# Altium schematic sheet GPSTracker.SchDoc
size B
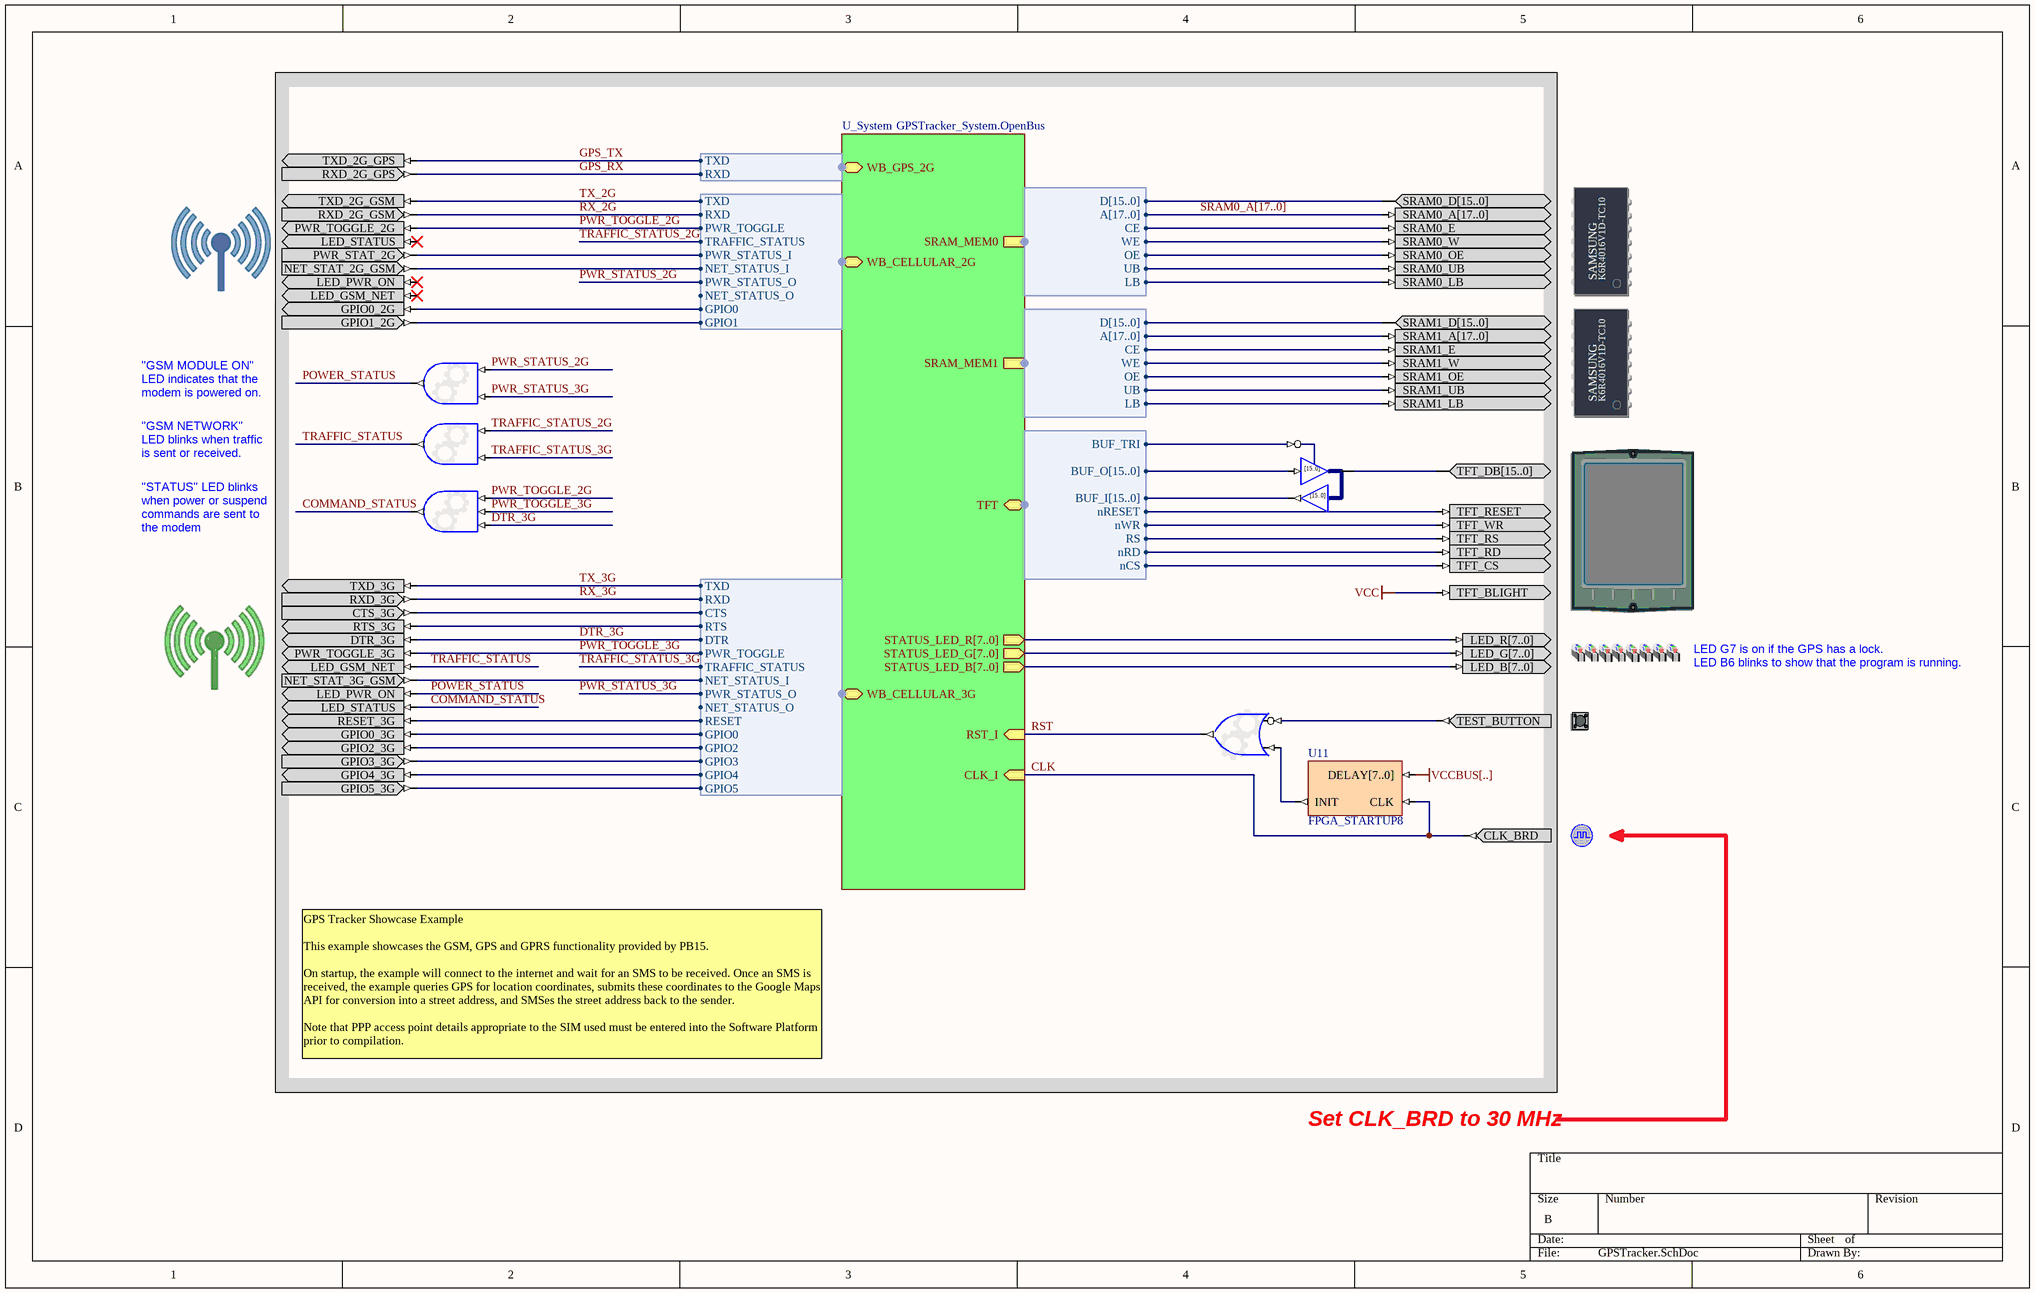
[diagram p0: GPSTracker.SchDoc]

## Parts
(Parts that share a designator on the sheet are numbered #1, #2 ... from top to bottom, then left to right.)
*  3G_GSM_GPS_COMP  (value not drawn)
?#1  2G_GPS_COMP  (value not drawn)
?#2  SRAM_DAUGHTER0  (value not drawn)
?#3  2G_GSM_COMP  (value not drawn)
?#4  SRAM_DAUGHTER1  (value not drawn)
?#5  TFT_LCD  (value not drawn)
?#6  LEDS_RGB  (value not drawn)
?#7  TEST_BUTTON  (value not drawn)
?#8  CLOCK_BOARD  (value not drawn)
U4  IOBUF16B  (value not drawn)
U6  OR2S  (value not drawn)
U7  AND3S  (value not drawn)
U8  AND2S  (value not drawn)
U9  AND2S  (value not drawn)
U11  FPGA_STARTUP8

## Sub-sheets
U_System = GPSTracker_System.OpenBus: SRAM_MEM0 (harness WB_MEM_CTRL_SRAM16_A18), SRAM_MEM1 (harness WB_MEM_CTRL_SRAM16_A18), RST_I (in), CLK_I (in), TFT (harness VGA32_ILI9320), WB_CELLULAR_2G (harness WB_CELLULAR_2G), WB_CELLULAR_3G (harness WB_CELLULAR_3G), WB_GPS_2G (harness WB_GPS_NMEA), STATUS_LED_R[7..0] (out), STATUS_LED_G[7..0] (out), STATUS_LED_B[7..0] (out)

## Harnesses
WB_MEM_CTRL_SRAM16_A18: D[15..0], A[17..0], CE, WE, OE, UB, LB
VGA32_ILI9320: BUF_TRI, BUF_O[15..0], BUF_I[15..0], nRESET, nWR, RS, nRD, nCS
WB_CELLULAR_2G: TXD, RXD, PWR_TOGGLE, TRAFFIC_STATUS, PWR_STATUS_I, NET_STATUS_I, PWR_STATUS_O, NET_STATUS_O, GPIO0, GPIO1
WB_CELLULAR_3G: TXD, RXD, CTS, RTS, DTR, PWR_TOGGLE, TRAFFIC_STATUS, NET_STATUS_I, PWR_STATUS_O, NET_STATUS_O, RESET, GPIO0, GPIO2, GPIO3, GPIO4, GPIO5
WB_GPS_NMEA: RXD, TXD

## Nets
VCC: ?#5.TFT_BLIGHT
VCCBUS[..]: U11.DELAY[7..0]
CLK: ?#8.CLK_BRD U11.CLK ; sheet U_System/CLK_I
COMMAND_STATUS: *.LED_STATUS U7.O
DTR_3G: *.DTR_3G U7.I2 ; sheet U_System/WB_CELLULAR_3G.DTR
GPS_RX: ?#1.RXD_2G_GPS ; sheet U_System/WB_GPS_2G.RXD
GPS_TX: ?#1.TXD_2G_GPS ; sheet U_System/WB_GPS_2G.TXD
POWER_STATUS: *.LED_PWR_ON U9.O
PWR_STATUS_2G: U9.I0 ; sheet U_System/WB_CELLULAR_2G.PWR_STATUS_O
PWR_STATUS_3G: U9.I1 ; sheet U_System/WB_CELLULAR_3G.PWR_STATUS_O
PWR_TOGGLE_2G: ?#3.PWR_TOGGLE_2G U7.I0 ; sheet U_System/WB_CELLULAR_2G.PWR_TOGGLE
PWR_TOGGLE_3G: *.PWR_TOGGLE_3G U7.I1 ; sheet U_System/WB_CELLULAR_3G.PWR_TOGGLE
RST: U6.O ; sheet U_System/RST_I
RX_2G: ?#3.RXD_2G_GSM ; sheet U_System/WB_CELLULAR_2G.RXD
RX_3G: *.RXD_3G ; sheet U_System/WB_CELLULAR_3G.RXD
TRAFFIC_STATUS: *.LED_GSM_NET U8.O
TRAFFIC_STATUS_2G: U8.I0 ; sheet U_System/WB_CELLULAR_2G.TRAFFIC_STATUS
TRAFFIC_STATUS_3G: U8.I1 ; sheet U_System/WB_CELLULAR_3G.TRAFFIC_STATUS
TX_2G: ?#3.TXD_2G_GSM ; sheet U_System/WB_CELLULAR_2G.TXD
TX_3G: *.TXD_3G ; sheet U_System/WB_CELLULAR_3G.TXD
Net*_CTS_3G: *.CTS_3G ; sheet U_System/WB_CELLULAR_3G.CTS
Net*_GPIO0_3G: *.GPIO0_3G ; sheet U_System/WB_CELLULAR_3G.GPIO0
Net*_GPIO2_3G: *.GPIO2_3G ; sheet U_System/WB_CELLULAR_3G.GPIO2
Net*_GPIO3_3G: *.GPIO3_3G ; sheet U_System/WB_CELLULAR_3G.GPIO3
Net*_GPIO4_3G: *.GPIO4_3G ; sheet U_System/WB_CELLULAR_3G.GPIO4
Net*_GPIO5_3G: *.GPIO5_3G ; sheet U_System/WB_CELLULAR_3G.GPIO5
Net*_NET_STAT_3G_GSM: *.NET_STAT_3G_GSM ; sheet U_System/WB_CELLULAR_3G.NET_STATUS_I
Net*_RESET_3G: *.RESET_3G ; sheet U_System/WB_CELLULAR_3G.RESET
Net*_RTS_3G: *.RTS_3G ; sheet U_System/WB_CELLULAR_3G.RTS
Net?#2_SRAM0_E: ?#2.SRAM0_E ; sheet U_System/SRAM_MEM0.CE
Net?#2_SRAM0_LB: ?#2.SRAM0_LB ; sheet U_System/SRAM_MEM0.LB
Net?#2_SRAM0_OE: ?#2.SRAM0_OE ; sheet U_System/SRAM_MEM0.OE
Net?#2_SRAM0_UB: ?#2.SRAM0_UB ; sheet U_System/SRAM_MEM0.UB
Net?#2_SRAM0_W: ?#2.SRAM0_W ; sheet U_System/SRAM_MEM0.WE
Net?#3_GPIO0_2G: ?#3.GPIO0_2G ; sheet U_System/WB_CELLULAR_2G.GPIO0
Net?#3_GPIO1_2G: ?#3.GPIO1_2G ; sheet U_System/WB_CELLULAR_2G.GPIO1
Net?#3_NET_STAT_2G_GSM: ?#3.NET_STAT_2G_GSM ; sheet U_System/WB_CELLULAR_2G.NET_STATUS_I
Net?#3_PWR_STAT_2G: ?#3.PWR_STAT_2G ; sheet U_System/WB_CELLULAR_2G.PWR_STATUS_I
Net?#4_SRAM1_E: ?#4.SRAM1_E ; sheet U_System/SRAM_MEM1.CE
Net?#4_SRAM1_LB: ?#4.SRAM1_LB ; sheet U_System/SRAM_MEM1.LB
Net?#4_SRAM1_OE: ?#4.SRAM1_OE ; sheet U_System/SRAM_MEM1.OE
Net?#4_SRAM1_UB: ?#4.SRAM1_UB ; sheet U_System/SRAM_MEM1.UB
Net?#4_SRAM1_W: ?#4.SRAM1_W ; sheet U_System/SRAM_MEM1.WE
Net?#5_TFT_CS: ?#5.TFT_CS ; sheet U_System/TFT.nCS
Net?#5_TFT_RD: ?#5.TFT_RD ; sheet U_System/TFT.nRD
Net?#5_TFT_RESET: ?#5.TFT_RESET ; sheet U_System/TFT.nRESET
Net?#5_TFT_RS: ?#5.TFT_RS ; sheet U_System/TFT.RS
Net?#5_TFT_WR: ?#5.TFT_WR ; sheet U_System/TFT.nWR
Net?#7_TEST_BUTTON: ?#7.TEST_BUTTON U6.I0
NetU4_T: U4.T ; sheet U_System/TFT.BUF_TRI
NetU6_I1: U6.I1 U11.INIT

Not connected (* = marked no-connect by the designer): ?#2 SRAM0_A[17..0] SRAM0_D[15..0]; ?#3 LED_GSM_NET* LED_PWR_ON* LED_STATUS*; ?#4 SRAM1_A[17..0] SRAM1_D[15..0]; ?#5 TFT_DB[15..0]; ?#6 LED_B[7..0] LED_G[7..0] LED_R[7..0]; U4 I[15..0] IO[15..0] O[15..0]

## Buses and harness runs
bus SRAM0_A[17..0]

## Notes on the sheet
- "GSM MODULE ON"
  LED indicates that the modem is powered on.
- "GSM NETWORK"
  LED blinks when traffic is sent or received.
- "STATUS" LED blinks when power or suspend commands are sent to the modem
- LED G7 is on if the GPS has a lock.
  LED B6 blinks to show that the program is running.
- GPS Tracker Showcase Example
  This example showcases the GSM, GPS and GPRS functionality provided by PB15.
  On startup, the example will connect to the internet and wait for an SMS to be received. Once an SMS is received, the example queries GPS for location coordinates, submits these coordinates to the Google Maps API for conversion into a street address, and SMSes the street address back to the sender.
  Note that PPP access point details appropriate to the SIM used must be entered into the Software Platform prior to compilation.
- Set CLK_BRD to 30 MHz

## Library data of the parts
* = 3G_GSM_GPS_COMP: 3G GSM/GPRS/GPS Component; PortComponent: TRUE
?#1 = 2G_GPS_COMP: 2G GPS Component; PortComponent: True
?#2 = SRAM_DAUGHTER0: Free Static RAM - Daughterboard; PortComponent: True
?#3 = 2G_GSM_COMP: 2G GSM/GPRS Component; PortComponent: True
?#4 = SRAM_DAUGHTER1: Free Static RAM - Daughterboard; PortComponent: True
?#5 = TFT_LCD: TFT LCD Panel; PortComponent: True
?#6 = LEDS_RGB: LEDS RGB; PortComponent: True
?#7 = TEST_BUTTON: Test / Reset Button; PortComponent: True
?#8 = CLOCK_BOARD: Global System Clock Supply; PortComponent: True
U4 = IOBUF16B: 16-Bit Input/Output Buffer, Bus Version; SubClass: IOBUF; Enable: Low; Control: Common Control T; PortSize: 16; ArchiveName: GENERIC; VHDLIB_SIM: GENERIC_LIB
U6 = GATE: Configurable Generic Gate; ConfiguratorName: GENERIC_GATE; ConfigurationParameters: {}Version[1.0]{}GateKind[OR]{}BusInput[False]{}GateInputType[Bit]{}GateOutputOption[Normal]{}BusWidth[8]{}RegisterOutputs[False]{}NegativeClockEdge[False]{}InputCount[2]{}InputInvert0[True]{}InputInvert1[False]{}
U7 = GATE: Configurable Generic Gate; ConfiguratorName: GENERIC_GATE; ConfigurationParameters: {}Version[1.1]{}GateKind[AND]{}BusInput[False]{}GateInputType[Bit]{}GateOutputOption[Normal]{}BusWidth[8]{}RegisterOutputs[False]{}NegativeClockEdge[False]{}InputCount[3]{}InputInvert0[False]{}InputInvert1[False]{}InputInvert2[False]{}
U8 U9 = GATE: Configurable Generic Gate; ConfiguratorName: GENERIC_GATE; ConfigurationParameters: {}Version[1.1]{}GateKind[AND]{}BusInput[False]{}GateInputType[Bit]{}GateOutputOption[Normal]{}BusWidth[8]{}RegisterOutputs[False]{}NegativeClockEdge[False]{}InputCount[2]{}InputInvert0[False]{}InputInvert1[False]{}
U11 = FPGA_STARTUP8: FPGA Startup With 8 Bit Delay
